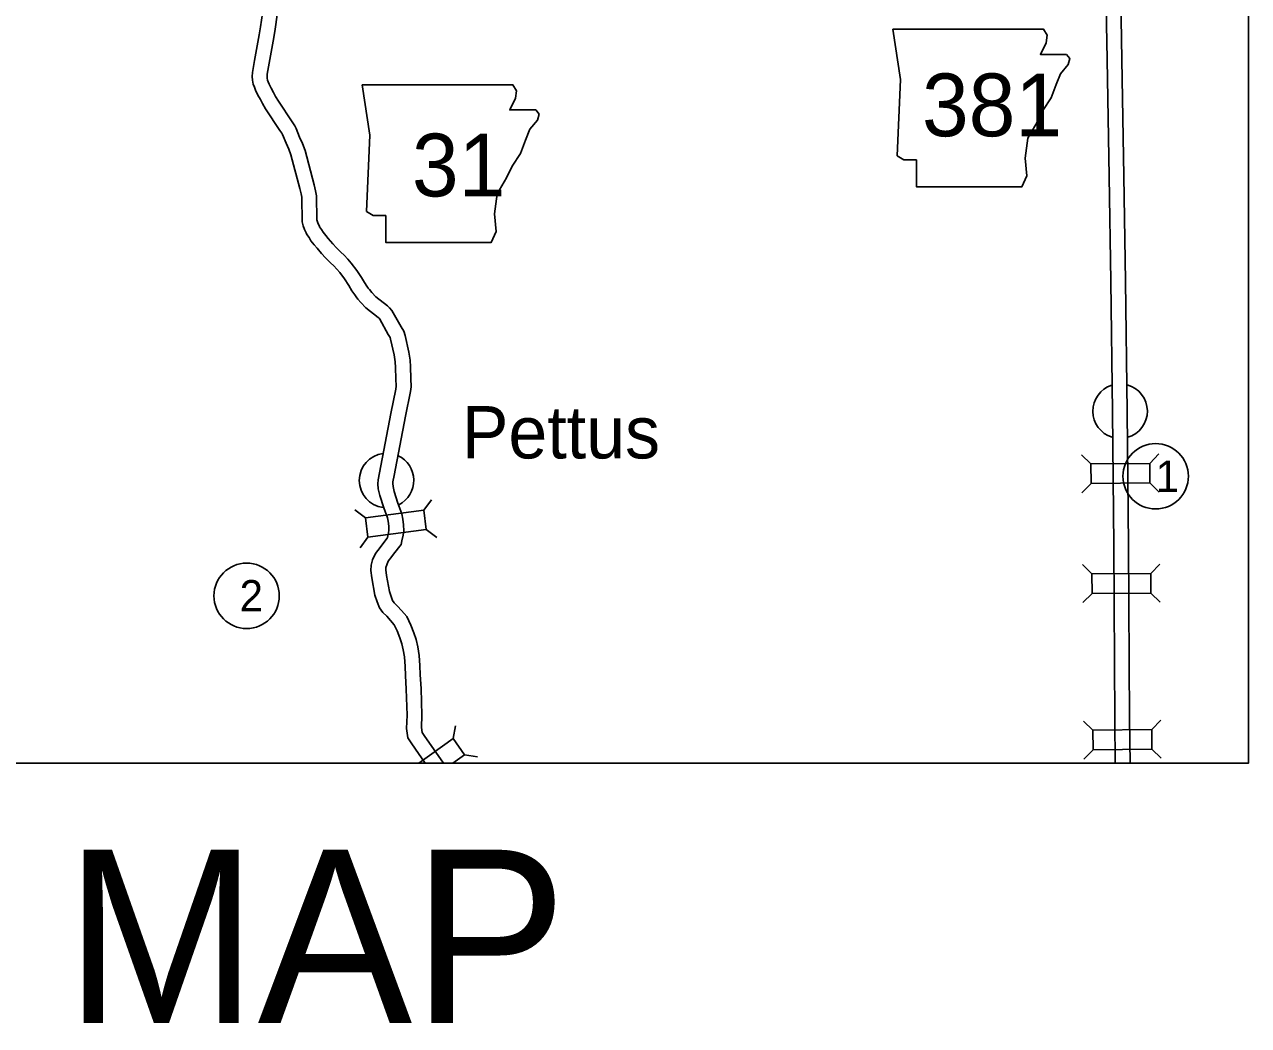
# Model space of a CAD drawing. Extents: x 1127717 to 1741049, y 2026793 to 2244711.
# Drawn here: x 1257093 to 1269452, y 2120946 to 2131052 of the extents above; entities that cross this region are included whole.
import ezdxf

# ---------------------------------------------------------------- set-up
doc = ezdxf.new("R2010")
doc.units = 0
for name, color, linetype in [('1', 7, 'Continuous'), ('10', 7, 'Continuous'), ('2', 7, 'Continuous'), ('20', 7, 'Continuous'), ('21', 7, 'Continuous'), ('24', 7, 'Continuous'), ('27', 7, 'Continuous')]:
    doc.layers.add(name, color=color, linetype=linetype)

msp = doc.modelspace()

# ---------------------------------------------------------------- linework, layer by layer
at = {"layer": '1'}
msp.add_lwpolyline([(1238438, 2155644), (1269452, 2155644), (1269452, 2123596), (1238438, 2123596)], close=True, dxfattribs=at)
at = {"layer": '10'}
for points in [[(1268077, 2127140), (1268060, 2128459), (1268043, 2129518), (1268024, 2130697), (1268001, 2131934), (1267983, 2133084), (1267967, 2134041), (1267952, 2134899), (1267946, 2135432)], [(1268227, 2127142), (1268210, 2128461), (1268193, 2129520), (1268174, 2130699), (1268151, 2131936), (1268133, 2133086), (1268117, 2134043), (1268102, 2134901), (1268096, 2135433)], [(1261003, 2123791), (1260965, 2123849), (1260951, 2123946), (1260956, 2124079), (1260948, 2124341), (1260939, 2124479), (1260935, 2124572), (1260930, 2124667), (1260918, 2124738), (1260902, 2124799), (1260882, 2124860), (1260855, 2124929), (1260825, 2124992), (1260788, 2125036), (1260750, 2125077), (1260711, 2125116), (1260677, 2125164), (1260653, 2125225), (1260631, 2125292), (1260601, 2125466), (1260590, 2125541), (1260594, 2125594), (1260608, 2125648), (1260636, 2125710), (1260683, 2125771), (1260700, 2125794), (1260756, 2125867), (1260757, 2125872), (1260768, 2125921), (1260772, 2125947), (1260770, 2125988), (1260764, 2126036), (1260757, 2126072), (1260720, 2126173), (1260682, 2126296), (1260665, 2126365), (1260661, 2126416), (1260663, 2126455), (1260679, 2126527), (1260793, 2127126), (1260842, 2127371), (1260846, 2127402), (1260844, 2127473), (1260840, 2127588), (1260836, 2127647), (1260826, 2127716), (1260790, 2127876), (1260785, 2127893), (1260766, 2127922), (1260680, 2128078), (1260673, 2128086), (1260663, 2128095), (1260539, 2128192), (1260489, 2128246), (1260459, 2128280), (1260442, 2128303), (1260427, 2128324), (1260399, 2128363), (1260367, 2128416), (1260323, 2128483), (1260276, 2128548), (1260246, 2128581), (1260215, 2128615), (1260182, 2128644), (1260131, 2128696), (1260093, 2128741), (1260047, 2128794), (1260018, 2128828), (1259985, 2128869), (1259966, 2128900), (1259945, 2128930), (1259936, 2128948), (1259919, 2128982), (1259907, 2129018), (1259896, 2129061), (1259892, 2129308), (1259886, 2129343), (1259873, 2129396), (1259783, 2129735), (1259762, 2129792), (1259734, 2129852), (1259697, 2129942), (1259691, 2129955), (1259672, 2129983), (1259527, 2130199), (1259497, 2130254), (1259476, 2130293), (1259450, 2130338), (1259427, 2130388), (1259414, 2130418), (1259402, 2130449), (1259394, 2130490), (1259392, 2130525), (1259395, 2130568), (1259415, 2130687), (1259463, 2130946), (1259475, 2131027), (1259496, 2131164)], [(1261129, 2123873), (1261109, 2123903), (1261101, 2123954), (1261106, 2124079), (1261097, 2124348), (1261089, 2124487), (1261085, 2124580), (1261079, 2124683), (1261065, 2124770), (1261046, 2124842), (1261023, 2124910), (1260993, 2124988), (1260952, 2125074), (1260900, 2125136), (1260858, 2125181), (1260826, 2125213), (1260810, 2125236), (1260794, 2125276), (1260777, 2125328), (1260749, 2125489), (1260741, 2125547), (1260742, 2125569), (1260750, 2125598), (1260766, 2125633), (1260802, 2125680), (1260819, 2125703), (1260896, 2125803), (1260904, 2125840), (1260916, 2125895), (1260922, 2125941), (1260920, 2126001), (1260912, 2126059), (1260903, 2126111), (1260863, 2126221), (1260827, 2126336), (1260814, 2126389), (1260811, 2126417), (1260813, 2126435), (1260826, 2126497), (1260940, 2127097), (1260991, 2127348), (1260996, 2127395), (1260994, 2127478), (1260990, 2127596), (1260986, 2127663), (1260973, 2127744), (1260935, 2127913), (1260923, 2127955), (1260895, 2127999), (1260803, 2128165), (1260779, 2128192), (1260759, 2128210), (1260641, 2128303), (1260600, 2128347), (1260576, 2128375), (1260564, 2128391), (1260549, 2128411), (1260525, 2128446), (1260494, 2128496), (1260447, 2128569), (1260393, 2128643), (1260356, 2128683), (1260320, 2128722), (1260286, 2128752), (1260242, 2128797), (1260207, 2128839), (1260160, 2128892), (1260134, 2128923), (1260109, 2128955), (1260091, 2128983), (1260073, 2129008), (1260070, 2129015), (1260058, 2129039), (1260051, 2129061), (1260046, 2129080), (1260042, 2129323), (1260032, 2129374), (1260019, 2129432), (1259926, 2129780), (1259901, 2129850), (1259871, 2129913), (1259835, 2130000), (1259824, 2130028), (1259796, 2130068), (1259656, 2130277), (1259629, 2130326), (1259608, 2130366), (1259583, 2130408), (1259563, 2130450), (1259553, 2130474), (1259547, 2130490), (1259543, 2130509), (1259542, 2130524), (1259544, 2130550), (1259563, 2130661), (1259611, 2130921), (1259623, 2131004), (1259645, 2131148)], [(1268077, 2127140), (1268091, 2125792), (1268101, 2124034)], [(1268227, 2127142), (1268241, 2125793), (1268251, 2124035)], [(1268101, 2124033), (1268105, 2123596)], [(1268251, 2124035), (1268255, 2123596)], [(1261127, 2123875), (1261324, 2123596)], [(1261005, 2123789), (1261140, 2123596)]]:
    msp.add_lwpolyline(points, dxfattribs=at)
at = {"layer": '20'}
for p, q in [((1267860, 2126615), (1267766, 2126707)), ((1268454, 2126621), (1268547, 2126716)), ((1267862, 2126417), (1267770, 2126323)), ((1268456, 2126423), (1268551, 2126331)), ((1261124, 2126149), (1261204, 2126254)), ((1260535, 2126071), (1260430, 2126152)), ((1261150, 2125953), (1261255, 2125872)), ((1260561, 2125875), (1260481, 2125770)), ((1267871, 2125507), (1267777, 2125600)), ((1268465, 2125510), (1268557, 2125604)), ((1267872, 2125309), (1267779, 2125215)), ((1268466, 2125312), (1268559, 2125219)), ((1261422, 2123842), (1261445, 2123972)), ((1267880, 2123928), (1267785, 2124020)), ((1268474, 2123934), (1268566, 2124028)), ((1267882, 2123730), (1267789, 2123635)), ((1268476, 2123736), (1268570, 2123644)), ((1261536, 2123680), (1261666, 2123657))]:
    msp.add_line(p, q, dxfattribs=at)
for points in [[(1267862, 2126417), (1268456, 2126423), (1268454, 2126621), (1267860, 2126615)], [(1261124, 2126149), (1260535, 2126071), (1260561, 2125875), (1261150, 2125953)], [(1267872, 2125309), (1268466, 2125312), (1268465, 2125510), (1267871, 2125507)], [(1267882, 2123730), (1268476, 2123736), (1268474, 2123934), (1267880, 2123928)]]:
    msp.add_lwpolyline(points, close=True, dxfattribs=at)
msp.add_lwpolyline([(1261417, 2123596), (1261536, 2123680), (1261422, 2123842), (1261073, 2123596)], dxfattribs=at)
at = {"layer": '21'}
for points in [[(1265862, 2131003), (1265938, 2130496), (1265904, 2129726), (1265971, 2129684), (1266098, 2129684), (1266098, 2129413), (1267164, 2129413), (1267215, 2129523), (1267198, 2129701), (1267223, 2129904), (1267316, 2130064), (1267376, 2130183), (1267460, 2130310), (1267511, 2130445), (1267553, 2130555), (1267629, 2130648), (1267646, 2130707), (1267613, 2130749), (1267350, 2130749), (1267409, 2130868), (1267418, 2130944), (1267383, 2131003)], [(1260504, 2130443), (1260580, 2129935), (1260546, 2129165), (1260614, 2129123), (1260741, 2129123), (1260741, 2128852), (1261806, 2128852), (1261857, 2128962), (1261840, 2129140), (1261866, 2129343), (1261959, 2129504), (1262018, 2129622), (1262102, 2129749), (1262153, 2129884), (1262195, 2129994), (1262272, 2130087), (1262288, 2130147), (1262255, 2130189), (1261992, 2130189), (1262052, 2130307), (1262060, 2130383), (1262025, 2130442)]]:
    msp.add_lwpolyline(points, close=True, dxfattribs=at)
at = {"layer": '24'}
for centre, start, end in [((1268155, 2127148), 107.928, 252.8104), ((1268155, 2127148), 286.2762, 74.8866), ((1260748, 2126449), 96.9183, 262.9448), ((1260748, 2126449), 297.0756, 64.8749)]:
    msp.add_arc(centre, 275, start, end, dxfattribs=at)
at = {"layer": '27'}
for centre in [(1268514, 2126491), (1259336, 2125284)]:
    msp.add_circle(centre, 330, dxfattribs=at)

# ---------------------------------------------------------------- texts
at = {"layer": '2'}
msp.add_text('VICINITY MAP', height=1750, dxfattribs=at).set_placement((1246966, 2120971))
at = {"layer": '21'}
for s, p in [('381', (1266155, 2129923)), ('31', (1261005, 2129316))]:
    msp.add_text(s, height=633.6, dxfattribs=at).set_placement(p)
at = {"layer": '24'}
msp.add_text('Pettus', height=528, dxfattribs=at).set_placement((1261508, 2126671))
at = {"layer": '27'}
for s, p in [('1', (1268514, 2126333)), ('2', (1259265, 2125126))]:
    msp.add_text(s, height=317, dxfattribs=at).set_placement(p)

doc.saveas('drawing.dxf')
